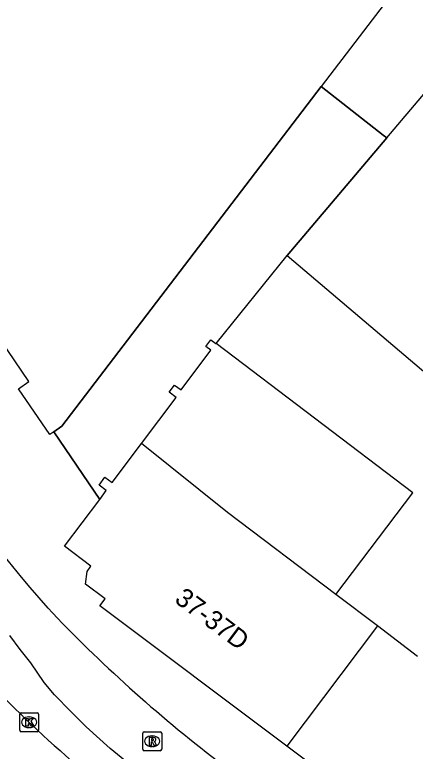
# Model space of a CAD drawing. Extents: x 161087 to 161922, y 382574 to 383873.
# Drawn here: x 161111.67 to 161132.83, y 383265.02 to 383303.94 of the extents above; entities that cross this region are included whole.
import ezdxf

# ---------------------------------------------------------------- set-up
doc = ezdxf.new("R2010")
doc.units = 0
for name, color, linetype in [('IMGEO_Fietspad_gesloten', 7, 'Continuous'), ('IMGEO_Kolk', 7, 'Continuous'), ('IMGEO_Pand', 7, 'Continuous'), ('IMGEO_Pand_nummerreeks', 7, 'Continuous'), ('IMGEO_Pand_overbouw', 7, 'Continuous'), ('IMGEO_Rijbaan_lokaal_gesloten', 7, 'Continuous'), ('IMGEO_Rioolput', 7, 'Continuous'), ('IMGEO_Voetgangersgebied_open', 7, 'Continuous')]:
    doc.layers.add(name, color=color, linetype=linetype)

msp = doc.modelspace()

# ---------------------------------------------------------------- linework, layer by layer
at = {"layer": 'IMGEO_Fietspad_gesloten'}
msp.add_lwpolyline([(161118.811, 383263.545), (161118.639, 383263.671), (161117.682, 383264.372), (161116.715, 383265.158), (161115.445, 383266.307), (161114.639, 383267.113), (161113.772, 383268), (161113.228, 383268.645), (161112.509, 383269.687), (161111.957, 383270.396), (161111.405, 383271.129)], dxfattribs=at)
for centre, radius, start, end in [((161168.197, 383321.02), 73.125, 203.48551, 221.47762), ((161168.637, 383324.915), 76.079, 223.45622, 232.55524)]:
    msp.add_arc(centre, radius, start, end, dxfattribs=at)
at = {"layer": 'IMGEO_Kolk'}
for p, q in [((161111.928, 383266.124), (161111.928, 383266.976)), ((161112.003, 383267.05), (161112.855, 383267.05)), ((161112.416, 383266.83), (161112.441, 383266.83)), ((161112.929, 383266.976), (161112.929, 383266.124)), ((161112.855, 383266.05), (161112.003, 383266.05)), ((161112.439, 383266.27), (161112.414, 383266.27))]:
    msp.add_line(p, q, dxfattribs=at)
for points in [[(161111.928, 383266.124), (161111.928, 383266.976)], [(161112.003, 383267.05), (161112.855, 383267.05)], [(161112.249, 383266.75), (161112.372, 383266.75), (161112.372, 383266.599), (161112.502, 383266.75), (161112.666, 383266.75), (161112.52, 383266.599), (161112.673, 383266.35), (161112.521, 383266.35), (161112.436, 383266.514), (161112.372, 383266.447), (161112.372, 383266.35), (161112.249, 383266.35), (161112.249, 383266.75)], [(161112.929, 383266.976), (161112.929, 383266.124)], [(161112.855, 383266.05), (161112.003, 383266.05)]]:
    msp.add_lwpolyline(points, dxfattribs=at)
for centre, start, end in [((161112.005, 383266.974), 91.552, 178.448), ((161112.005, 383266.974), 91.552, 178.448), ((161112.853, 383266.974), 1.552, 88.448), ((161112.853, 383266.974), 1.552, 88.448), ((161112.005, 383266.126), 181.552, 268.448), ((161112.005, 383266.126), 181.552, 268.448), ((161112.853, 383266.126), 271.552, 358.448), ((161112.853, 383266.126), 271.552, 358.448)]:
    msp.add_arc(centre, 0.0765, start, end, dxfattribs=at)
for centre, major_axis, ratio, start_param, end_param in [((161112.415, 383266.55), (-0.387, 0.002), 0.722429, 4.712389, 7.853982), ((161112.44, 383266.55), (-0.39, 0.002), 0.717154, 1.570796, 4.712389)]:
    msp.add_ellipse(centre, major_axis=major_axis, ratio=ratio, start_param=start_param, end_param=end_param, dxfattribs=at)
at = {"layer": 'IMGEO_Pand'}
for points in [[(161130.514, 383320.127), (161129.583, 383317.196), (161128.987, 383317.389), (161127.383, 383312.427), (161127.939, 383312.247), (161127.014, 383309.387), (161126.455, 383309.568), (161125.784, 383307.492), (161130.564, 383305.947), (161131.65, 383305.119), (161127.864, 383300.155)], [(161113.732, 383281.897), (161113.514, 383281.749), (161111.862, 383284.179), (161112.409, 383284.551), (161109.47, 383288.875), (161108.928, 383288.506), (161107.278, 383290.932), (161107.804, 383291.289), (161104.908, 383295.55), (161104.359, 383295.177), (161102.047, 383298.578), (161103.491, 383303.042), (161104.031, 383302.867), (161105.613, 383307.759)], [(161131.326, 383297.432), (161135.611, 383302.499), (161137.707, 383304.978)], [(161113.732, 383281.897), (161114.163, 383282.19), (161127.864, 383300.155)], [(161131.326, 383297.432), (161126.068, 383291.213)], [(161126.068, 383291.213), (161140.496, 383278.979)], [(161118.366, 383281.284), (161120.192, 383283.717), (161119.83, 383283.989), (161120.117, 383284.372), (161120.461, 383284.114), (161122.035, 383286.212), (161121.771, 383286.41), (161122.038, 383286.768), (161122.301, 383286.568), (161122.314, 383286.558)], [(161128.633, 383273.303), (161132.707, 383278.674), (161122.314, 383286.558)], [(161116.16, 383278.329), (161116.507, 383278.792), (161116.12, 383279.083), (161116.431, 383279.497), (161116.81, 383279.212), (161118.366, 383281.284)], [(161128.633, 383273.303), (161122.914, 383277.631), (161118.366, 383281.284)], [(161126.05, 383265.285), (161116.167, 383272.702), (161116.445, 383273.072), (161115.411, 383273.848), (161115.493, 383274.524), (161115.697, 383274.796), (161114.296, 383275.847), (161116.16, 383278.329)], [(161130.831, 383271.64), (161128.633, 383273.303)], [(161130.831, 383271.64), (161126.05, 383265.285)], [(161132.96, 383270.029), (161130.831, 383271.64)], [(161138.093, 383256.246), (161126.05, 383265.285)]]:
    msp.add_lwpolyline(points, dxfattribs=at)
at = {"layer": 'IMGEO_Pand_overbouw'}
msp.add_lwpolyline([(161127.864, 383300.155), (161114.163, 383282.19), (161113.732, 383281.897), (161116.16, 383278.329), (161116.507, 383278.792), (161116.12, 383279.083), (161116.431, 383279.497), (161116.81, 383279.212), (161118.366, 383281.284), (161120.192, 383283.717), (161119.83, 383283.989), (161120.117, 383284.372), (161120.461, 383284.114), (161122.035, 383286.212), (161121.771, 383286.41), (161121.77, 383286.411), (161122.038, 383286.768), (161122.301, 383286.568), (161122.314, 383286.558), (161126.068, 383291.213), (161131.326, 383297.432), (161131.142, 383297.576)], close=True, dxfattribs=at)
at = {"layer": 'IMGEO_Rijbaan_lokaal_gesloten'}
msp.add_arc((161155.114, 383311.482), 61.979, 224.37685, 230.40125, dxfattribs=at)
at = {"layer": 'IMGEO_Rioolput'}
for p, q in [((161118.431, 383265.12), (161118.431, 383265.972)), ((161118.506, 383266.046), (161119.358, 383266.046)), ((161119.432, 383265.972), (161119.432, 383265.12)), ((161118.919, 383265.826), (161118.944, 383265.826)), ((161118.942, 383265.266), (161118.917, 383265.266)), ((161119.358, 383265.046), (161118.506, 383265.046))]:
    msp.add_line(p, q, dxfattribs=at)
for points in [[(161118.431, 383265.12), (161118.431, 383265.972)], [(161118.506, 383266.046), (161119.358, 383266.046)], [(161119.432, 383265.972), (161119.432, 383265.12)], [(161119.02, 383265.744), (161118.768, 383265.746), (161118.768, 383265.346)], [(161118.946, 383265.665), (161118.892, 383265.665), (161118.892, 383265.584)], [(161118.892, 383265.584), (161118.944, 383265.584)], [(161118.768, 383265.346), (161118.892, 383265.346), (161118.892, 383265.508), (161118.903, 383265.508)], [(161118.95, 383265.479), (161119.021, 383265.346), (161119.161, 383265.346), (161119.096, 383265.472)], [(161119.358, 383265.046), (161118.506, 383265.046)]]:
    msp.add_lwpolyline(points, dxfattribs=at)
for centre, radius, start, end in [((161118.508, 383265.97), 0.0765, 91.552, 178.448), ((161118.508, 383265.97), 0.0765, 91.552, 178.448), ((161119.356, 383265.97), 0.0765, 1.552, 88.448), ((161119.356, 383265.97), 0.0765, 1.552, 88.448), ((161118.928, 383265.773), 0.19, 274.7715, 282.9687), ((161118.952, 383265.569), 0.0964, 77.0061, 93.1865), ((161118.966, 383265.626), 0.0378, 276.6634, 79.6772), ((161119.019, 383265.634), 0.109, 350.3612, 89.416), ((161119.017, 383265.634), 0.112, 277.5842, 350.9817), ((161118.902, 383265.455), 0.0533, 26.0293, 88.6989), ((161119.001, 383265.419), 0.108, 29.5134, 73.7905), ((161118.508, 383265.122), 0.0765, 181.552, 268.448), ((161118.508, 383265.122), 0.0765, 181.552, 268.448), ((161119.356, 383265.122), 0.0765, 271.552, 358.448), ((161119.356, 383265.122), 0.0765, 271.552, 358.448)]:
    msp.add_arc(centre, radius, start, end, dxfattribs=at)
for centre, major_axis, ratio, start_param, end_param in [((161118.918, 383265.546), (-0.387, 0.002), 0.722429, 4.712389, 7.853982), ((161118.943, 383265.546), (-0.39, 0.002), 0.717154, 1.570796, 4.712389)]:
    msp.add_ellipse(centre, major_axis=major_axis, ratio=ratio, start_param=start_param, end_param=end_param, dxfattribs=at)
at = {"layer": 'IMGEO_Voetgangersgebied_open'}
for points in [[(161127.864, 383300.155), (161131.142, 383297.576), (161131.326, 383297.432)], [(161122.314, 383286.558), (161126.068, 383291.213)], [(161116.16, 383278.329), (161113.732, 383281.897)]]:
    msp.add_lwpolyline(points, dxfattribs=at)

# ---------------------------------------------------------------- texts
at = {"layer": 'IMGEO_Pand_nummerreeks'}
msp.add_text('37-37D', height=1, rotation=323.1106, dxfattribs=at).set_placement((161120.056, 383272.934))

doc.saveas('drawing.dxf')
